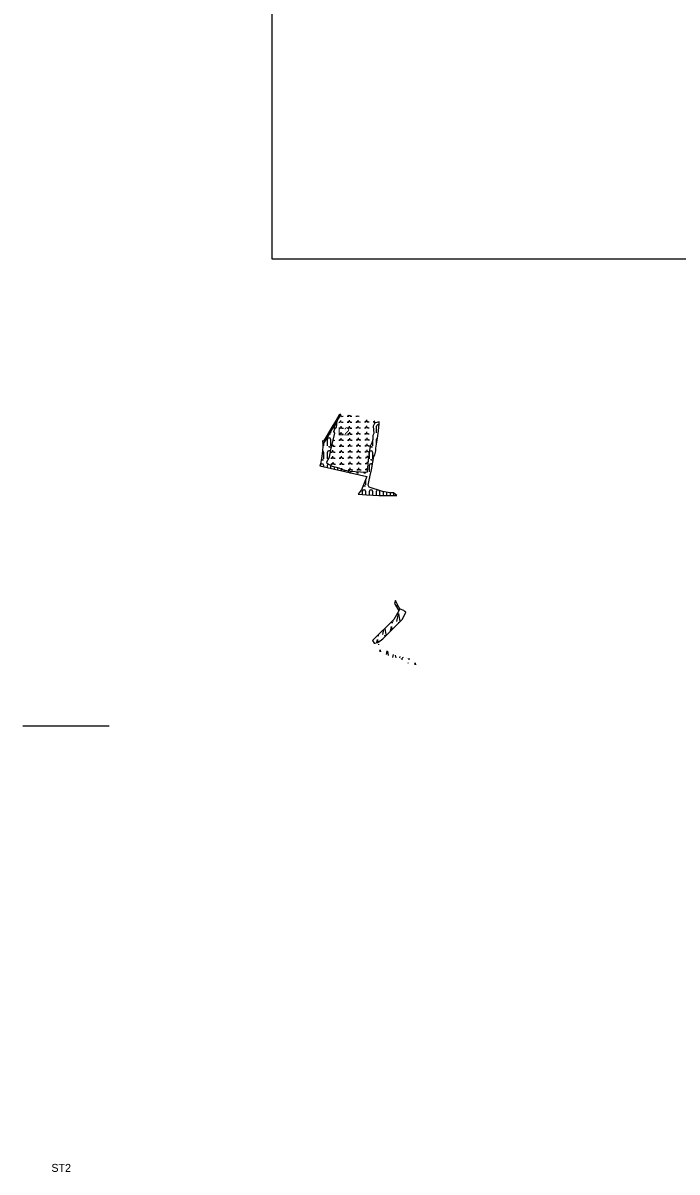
# Model space of a CAD drawing. Extents: x -557103 to -548162, y -1041918 to -1033974.
# Drawn here: x -556985 to -555351, y -1041918 to -1039045 of the extents above; entities that cross this region are included whole.
import ezdxf

# ---------------------------------------------------------------- set-up
doc = ezdxf.new("R2010")
doc.units = 0
for name, color, linetype in [('Vrstva 12', 7, 'Continuous'), ('Vrstva 13', 7, 'Continuous'), ('Vrstva 16', 7, 'Continuous'), ('Vrstva 63', 7, 'Continuous'), ('Vrstva 9', 7, 'Continuous')]:
    doc.layers.add(name, color=color, linetype=linetype)

msp = doc.modelspace()

# ---------------------------------------------------------------- linework, layer by layer
at = {"layer": 'Vrstva 12'}
for p, q in [((-556192.9, -1040028.7), (-556192.2, -1040028.7)), ((-556192.2, -1040028.7), (-556192.7, -1040027.7)), ((-556190.7, -1040028.2), (-556190.8, -1040023.8)), ((-556189.4, -1040028.7), (-556188.3, -1040026.3)), ((-556189.4, -1040028.7), (-556184.9, -1040028.6)), ((-556174.9, -1040028.4), (-556170.8, -1040028.3)), ((-556170.8, -1040028.3), (-556171.8, -1040026)), ((-556169.2, -1040027.8), (-556169.3, -1040025.4)), ((-556167.9, -1040028.3), (-556166.8, -1040026)), ((-556167.9, -1040028.3), (-556163.4, -1040028.3)), ((-556153.4, -1040028), (-556149.3, -1040028)), ((-556149.3, -1040028), (-556149.7, -1040027)), ((-556147.8, -1040027.4), (-556147.8, -1040027.4)), ((-556146.4, -1040028), (-556146.3, -1040027.7)), ((-556146.4, -1040028), (-556144.9, -1040027.9)), ((-556126, -1040042), (-556126.1, -1040037.6)), ((-556208.2, -1040066.7), (-556204.8, -1040058.2)), ((-556206.6, -1040062.6), (-556206.6, -1040053)), ((-556204.8, -1040058.2), (-556201.5, -1040055.4)), ((-556201.5, -1040055.4), (-556199.6, -1040039.7)), ((-556196.1, -1040043.7), (-556192, -1040043.6)), ((-556195.9, -1040058.6), (-556191.7, -1040058.5)), ((-556192, -1040043.6), (-556193, -1040041.3)), ((-556191.7, -1040058.5), (-556192.8, -1040056.2)), ((-556190.5, -1040043.1), (-556190.5, -1040038.7)), ((-556190.2, -1040058), (-556190.3, -1040053.6)), ((-556189.1, -1040043.6), (-556188, -1040041.2)), ((-556189.1, -1040043.6), (-556184.7, -1040043.6)), ((-556188.9, -1040058.5), (-556187.8, -1040056.2)), ((-556188.9, -1040058.5), (-556184.4, -1040058.5)), ((-556174.7, -1040043.3), (-556170.5, -1040043.2)), ((-556174.4, -1040058.2), (-556170.2, -1040058.1)), ((-556170.5, -1040043.2), (-556171.5, -1040040.9)), ((-556170.2, -1040058.1), (-556171.3, -1040055.8)), ((-556169, -1040042.7), (-556169.1, -1040038.4)), ((-556168.7, -1040057.6), (-556168.8, -1040053.3)), ((-556167.6, -1040043.3), (-556166.6, -1040040.9)), ((-556167.6, -1040043.3), (-556163.2, -1040043.2)), ((-556167.4, -1040058.2), (-556166.3, -1040055.8)), ((-556167.4, -1040058.2), (-556162.9, -1040058.1)), ((-556153.2, -1040042.9), (-556149, -1040042.9)), ((-556152.9, -1040057.8), (-556148.8, -1040057.8)), ((-556149, -1040042.9), (-556150.1, -1040040.5)), ((-556148.8, -1040057.8), (-556149.8, -1040055.4)), ((-556147.5, -1040042.3), (-556147.6, -1040038)), ((-556147.2, -1040057.2), (-556147.3, -1040052.9)), ((-556146.2, -1040042.9), (-556145.1, -1040040.5)), ((-556146.2, -1040042.9), (-556141.7, -1040042.8)), ((-556145.9, -1040057.8), (-556144.8, -1040055.4)), ((-556145.9, -1040057.8), (-556141.4, -1040057.7)), ((-556131.7, -1040042.6), (-556127.5, -1040042.5)), ((-556131.4, -1040057.5), (-556127.3, -1040057.4)), ((-556127.5, -1040042.5), (-556128.6, -1040040.1)), ((-556127.3, -1040057.4), (-556128.3, -1040055.1)), ((-556125.8, -1040056.9), (-556125.8, -1040052.5)), ((-556124.7, -1040042.5), (-556123.6, -1040040.1)), ((-556124.7, -1040042.5), (-556120.2, -1040042.4)), ((-556124.4, -1040057.4), (-556123.3, -1040055)), ((-556124.4, -1040057.4), (-556120, -1040057.3)), ((-556110.2, -1040042.2), (-556106.1, -1040042.1)), ((-556106.2, -1040046.2), (-556110.1, -1040053.6)), ((-556110.1, -1040053.6), (-556108.5, -1040071.6)), ((-556110, -1040057.1), (-556109.8, -1040057.1)), ((-556106.1, -1040042.1), (-556107.1, -1040039.8)), ((-556104.3, -1040044.9), (-556106.2, -1040046.2)), ((-556095.2, -1040042.7), (-556104.3, -1040044.9)), ((-556101.6, -1040069.5), (-556101.6, -1040053)), ((-556099.4, -1040083), (-556097, -1040065.3)), ((-556097, -1040065.3), (-556095.3, -1040047.6)), ((-556095.3, -1040047.6), (-556095.2, -1040042.7)), ((-556224.1, -1040102.1), (-556224.1, -1040085.6)), ((-556216.6, -1040067.1), (-556216.6, -1040069.5)), ((-556216.6, -1040085.6), (-556216.6, -1040102.1)), ((-556216.1, -1040112.6), (-556205.6, -1040070.7)), ((-556209.8, -1040088.7), (-556208.7, -1040086.3)), ((-556209.8, -1040088.7), (-556205.4, -1040088.6)), ((-556205.6, -1040070.7), (-556208.2, -1040066.7)), ((-556206.6, -1040069.5), (-556206.6, -1040069.2)), ((-556206.4, -1040073.7), (-556205.6, -1040073.7)), ((-556195.6, -1040073.5), (-556191.5, -1040073.4)), ((-556195.4, -1040088.4), (-556191.2, -1040088.3)), ((-556191.5, -1040073.4), (-556192.5, -1040071.1)), ((-556191.2, -1040088.3), (-556192.2, -1040086)), ((-556189.9, -1040072.9), (-556190, -1040068.6)), ((-556189.7, -1040087.8), (-556189.8, -1040083.5)), ((-556188.6, -1040073.4), (-556187.5, -1040071.1)), ((-556188.6, -1040073.4), (-556184.1, -1040073.4)), ((-556188.3, -1040088.3), (-556187.3, -1040086)), ((-556188.3, -1040088.3), (-556183.9, -1040088.3)), ((-556174.1, -1040073.1), (-556170, -1040073.1)), ((-556173.9, -1040088), (-556169.7, -1040088)), ((-556170, -1040073.1), (-556171, -1040070.7)), ((-556169.7, -1040088), (-556170.8, -1040085.6)), ((-556168.5, -1040072.5), (-556168.5, -1040068.2)), ((-556168.2, -1040087.4), (-556168.3, -1040083.1)), ((-556167.1, -1040073.1), (-556166, -1040070.7)), ((-556167.1, -1040073.1), (-556162.7, -1040073)), ((-556166.9, -1040088), (-556165.8, -1040085.6)), ((-556166.9, -1040088), (-556162.4, -1040087.9)), ((-556152.7, -1040072.7), (-556148.5, -1040072.7)), ((-556152.4, -1040087.7), (-556148.2, -1040087.6)), ((-556148.5, -1040072.7), (-556149.5, -1040070.3)), ((-556148.2, -1040087.6), (-556149.3, -1040085.2)), ((-556147, -1040072.2), (-556147.1, -1040067.8)), ((-556146.7, -1040087.1), (-556146.8, -1040082.7)), ((-556145.6, -1040072.7), (-556144.6, -1040070.3)), ((-556145.6, -1040072.7), (-556141.2, -1040072.6)), ((-556145.4, -1040087.6), (-556144.3, -1040085.2)), ((-556145.4, -1040087.6), (-556140.9, -1040087.5)), ((-556131.2, -1040072.4), (-556127, -1040072.3)), ((-556130.9, -1040087.3), (-556126.8, -1040087.2)), ((-556127, -1040072.3), (-556128.1, -1040070)), ((-556126.8, -1040087.2), (-556127.8, -1040084.9)), ((-556125.5, -1040071.8), (-556125.6, -1040067.4)), ((-556125.2, -1040086.7), (-556125.3, -1040082.3)), ((-556124.2, -1040072.3), (-556123.1, -1040069.9)), ((-556124.2, -1040072.3), (-556119.7, -1040072.2)), ((-556123.9, -1040087.2), (-556122.8, -1040084.8)), ((-556123.9, -1040087.2), (-556119.4, -1040087.1)), ((-556112.9, -1040095.2), (-556117.3, -1040102.9)), ((-556110.6, -1040086.2), (-556112.9, -1040095.2)), ((-556111.6, -1040090), (-556111.6, -1040102.1)), ((-556110.4, -1040076.8), (-556110.6, -1040086.2)), ((-556108.5, -1040071.6), (-556110.4, -1040076.8)), ((-556103.5, -1040108.5), (-556099.4, -1040083)), ((-556101.6, -1040096.7), (-556101.6, -1040085.6)), ((-556236.5, -1040115.5), (-556239.3, -1040133.8)), ((-556235.5, -1040102.4), (-556236.5, -1040115.5)), ((-556235.4, -1040097.9), (-556235.5, -1040102.4)), ((-556234.1, -1040095.8), (-556234.1, -1040102.1)), ((-556234.1, -1040118.1), (-556234.1, -1040134.6)), ((-556224.1, -1040134.6), (-556224.1, -1040118.1)), ((-556219, -1040130.7), (-556216.1, -1040112.6)), ((-556216.3, -1040118.6), (-556212.2, -1040118.5)), ((-556213.9, -1040103.6), (-556212.4, -1040103.6)), ((-556212.4, -1040103.6), (-556213.3, -1040101.5)), ((-556212.2, -1040118.5), (-556213.2, -1040116.2)), ((-556210.9, -1040103.1), (-556211, -1040098.7)), ((-556210.6, -1040118), (-556210.7, -1040113.6)), ((-556209.6, -1040103.6), (-556208.5, -1040101.2)), ((-556209.6, -1040103.6), (-556205.1, -1040103.5)), ((-556209.3, -1040118.5), (-556208.2, -1040116.1)), ((-556209.3, -1040118.5), (-556204.8, -1040118.5)), ((-556195.1, -1040103.3), (-556190.9, -1040103.2)), ((-556194.8, -1040118.2), (-556190.7, -1040118.1)), ((-556190.9, -1040103.2), (-556192, -1040100.9)), ((-556190.7, -1040118.1), (-556191.7, -1040115.8)), ((-556189.4, -1040102.7), (-556189.5, -1040098.4)), ((-556189.2, -1040117.6), (-556189.2, -1040113.3)), ((-556188.1, -1040103.2), (-556187, -1040100.9)), ((-556188.1, -1040103.2), (-556183.6, -1040103.2)), ((-556187.8, -1040118.2), (-556186.7, -1040115.8)), ((-556187.8, -1040118.2), (-556183.4, -1040118.1)), ((-556173.6, -1040102.9), (-556169.5, -1040102.9)), ((-556173.4, -1040117.8), (-556169.2, -1040117.8)), ((-556169.5, -1040102.9), (-556170.5, -1040100.5)), ((-556169.2, -1040117.8), (-556170.2, -1040115.4)), ((-556167.9, -1040102.3), (-556168, -1040098)), ((-556167.7, -1040117.2), (-556167.8, -1040112.9)), ((-556166.6, -1040102.9), (-556165.5, -1040100.5)), ((-556166.6, -1040102.9), (-556162.1, -1040102.8)), ((-556166.3, -1040117.8), (-556165.3, -1040115.4)), ((-556166.3, -1040117.8), (-556161.9, -1040117.7)), ((-556152.1, -1040102.6), (-556148, -1040102.5)), ((-556151.9, -1040117.5), (-556147.7, -1040117.4)), ((-556148, -1040102.5), (-556149, -1040100.1)), ((-556147.7, -1040117.4), (-556148.8, -1040115)), ((-556146.5, -1040102), (-556146.5, -1040097.6)), ((-556146.2, -1040116.9), (-556146.3, -1040112.5)), ((-556145.1, -1040102.5), (-556144, -1040100.1)), ((-556145.1, -1040102.5), (-556140.7, -1040102.4)), ((-556144.9, -1040117.4), (-556143.8, -1040115)), ((-556144.9, -1040117.4), (-556140.4, -1040117.3)), ((-556130.7, -1040102.2), (-556126.5, -1040102.1)), ((-556130.4, -1040117.1), (-556126.2, -1040117)), ((-556126.5, -1040102.1), (-556127.5, -1040099.8)), ((-556126.2, -1040117), (-556127.3, -1040114.7)), ((-556125, -1040101.6), (-556125.1, -1040097.2)), ((-556124.7, -1040116.5), (-556124.8, -1040112.1)), ((-556123.6, -1040102.1), (-556122.6, -1040099.7)), ((-556123.6, -1040102.1), (-556119.2, -1040102)), ((-556123.4, -1040117), (-556122.3, -1040114.6)), ((-556123.4, -1040117), (-556119.6, -1040117)), ((-556117.3, -1040102.9), (-556120.8, -1040124.4)), ((-556119.1, -1040134.6), (-556119.1, -1040118.1)), ((-556111.6, -1040118.1), (-556111.6, -1040134.6)), ((-556105.6, -1040124.8), (-556103.3, -1040114.8)), ((-556103.3, -1040114.8), (-556103.5, -1040108.5)), ((-556241.8, -1040147.6), (-556242.9, -1040152.6)), ((-556242.9, -1040152.6), (-556125.7, -1040179.3)), ((-556239.3, -1040133.8), (-556241.8, -1040147.6)), ((-556241.6, -1040152.9), (-556241.6, -1040150.6)), ((-556234.1, -1040150.6), (-556234.1, -1040154.6)), ((-556225.7, -1040142.2), (-556219, -1040130.7)), ((-556225.1, -1040146.5), (-556225.7, -1040142.2)), ((-556211.4, -1040154), (-556225.1, -1040146.5)), ((-556224.1, -1040156.9), (-556224.1, -1040150.6)), ((-556216.6, -1040151.2), (-556216.6, -1040158.6)), ((-556216.1, -1040133.5), (-556211.9, -1040133.4)), ((-556215.8, -1040148.4), (-556211.6, -1040148.3)), ((-556211.9, -1040133.4), (-556212.9, -1040131.1)), ((-556211.6, -1040148.3), (-556212.7, -1040146)), ((-556210.4, -1040132.9), (-556210.5, -1040128.6)), ((-556210.1, -1040147.8), (-556210.2, -1040143.5)), ((-556209, -1040133.4), (-556208, -1040131.1)), ((-556209, -1040133.4), (-556204.6, -1040133.4)), ((-556208.8, -1040148.3), (-556207.7, -1040146)), ((-556208.8, -1040148.3), (-556204.3, -1040148.3)), ((-556194.6, -1040133.1), (-556190.4, -1040133)), ((-556194.3, -1040148), (-556190.2, -1040148)), ((-556190.4, -1040133), (-556191.5, -1040130.7)), ((-556190.2, -1040148), (-556191.2, -1040145.6)), ((-556188.9, -1040132.5), (-556189, -1040128.2)), ((-556188.6, -1040147.4), (-556188.7, -1040143.1)), ((-556187.6, -1040133.1), (-556186.5, -1040130.7)), ((-556187.6, -1040133.1), (-556183.1, -1040133)), ((-556187.3, -1040148), (-556186.2, -1040145.6)), ((-556187.3, -1040148), (-556182.8, -1040147.9)), ((-556173.1, -1040132.7), (-556168.9, -1040132.7)), ((-556172.8, -1040147.7), (-556168.7, -1040147.6)), ((-556168.9, -1040132.7), (-556170, -1040130.3)), ((-556168.7, -1040147.6), (-556169.7, -1040145.2)), ((-556167.4, -1040132.1), (-556167.5, -1040127.8)), ((-556167.2, -1040147.1), (-556167.2, -1040142.7)), ((-556166.1, -1040132.7), (-556165, -1040130.3)), ((-556166.1, -1040132.7), (-556161.6, -1040132.6)), ((-556165.8, -1040147.6), (-556164.7, -1040145.2)), ((-556165.8, -1040147.6), (-556161.4, -1040147.5)), ((-556151.6, -1040132.4), (-556147.5, -1040132.3)), ((-556151.4, -1040147.3), (-556147.2, -1040147.2)), ((-556147.5, -1040132.3), (-556148.5, -1040130)), ((-556147.2, -1040147.2), (-556148.2, -1040144.9)), ((-556145.9, -1040131.8), (-556146, -1040127.4)), ((-556145.7, -1040146.7), (-556145.8, -1040142.3)), ((-556144.6, -1040132.3), (-556143.5, -1040129.9)), ((-556144.6, -1040132.3), (-556140.1, -1040132.2)), ((-556144.3, -1040147.2), (-556143.3, -1040144.8)), ((-556144.3, -1040147.2), (-556139.9, -1040147.1)), ((-556130.1, -1040132), (-556126, -1040131.9)), ((-556129.9, -1040146.9), (-556125.7, -1040146.8)), ((-556126, -1040131.9), (-556127, -1040129.6)), ((-556125.7, -1040146.8), (-556126.7, -1040144.5)), ((-556124.5, -1040131.4), (-556124.5, -1040127.1)), ((-556123.2, -1040146.8), (-556124.5, -1040158.1)), ((-556124.2, -1040146.3), (-556124.3, -1040142)), ((-556120.8, -1040124.4), (-556123.2, -1040146.8)), ((-556123.1, -1040131.9), (-556122, -1040129.6)), ((-556123.1, -1040131.9), (-556121.6, -1040131.9)), ((-556120.8, -1040124.4), (-556120.8, -1040124.4)), ((-556119.1, -1040167.1), (-556119.1, -1040150.6)), ((-556114.2, -1040162.7), (-556107.9, -1040129.2)), ((-556107.9, -1040129.2), (-556105.6, -1040124.8)), ((-556194.9, -1040158.3), (-556211.4, -1040154)), ((-556206.6, -1040160.9), (-556206.6, -1040155.3)), ((-556199.1, -1040157.2), (-556199.1, -1040162.6)), ((-556183.9, -1040163.1), (-556194.9, -1040158.3)), ((-556189.1, -1040164.9), (-556189.1, -1040160.8)), ((-556188.4, -1040161.1), (-556188.5, -1040158)), ((-556186.6, -1040161.9), (-556186, -1040160.5)), ((-556184.6, -1040162.8), (-556182.6, -1040162.8)), ((-556167.1, -1040166.2), (-556183.9, -1040163.1)), ((-556181.6, -1040163.5), (-556181.6, -1040166.6)), ((-556172.6, -1040162.6), (-556168.4, -1040162.5)), ((-556171.6, -1040167.1), (-556171.6, -1040165.4)), ((-556168.4, -1040162.5), (-556169.5, -1040160.1)), ((-556141.4, -1040168.6), (-556167.1, -1040166.2)), ((-556166.9, -1040162), (-556167, -1040157.6)), ((-556165.6, -1040162.5), (-556164.5, -1040160.1)), ((-556165.6, -1040162.5), (-556161.1, -1040162.4)), ((-556164.1, -1040166.5), (-556164.1, -1040167.1)), ((-556151.1, -1040162.2), (-556146.9, -1040162.1)), ((-556146.9, -1040162.1), (-556148, -1040159.8)), ((-556145.4, -1040161.6), (-556145.5, -1040157.2)), ((-556144.1, -1040162.1), (-556143, -1040159.7)), ((-556144.1, -1040162.1), (-556139.6, -1040162)), ((-556128.1, -1040168.9), (-556141.4, -1040168.6)), ((-556125.7, -1040179.3), (-556139.2, -1040212)), ((-556129.6, -1040161.8), (-556125.5, -1040161.7)), ((-556124.7, -1040168.3), (-556128.1, -1040168.9)), ((-556125.5, -1040161.7), (-556126.5, -1040159.4)), ((-556124.5, -1040158.1), (-556124.7, -1040168.3)), ((-556122.5, -1040200.7), (-556118.3, -1040179.7)), ((-556118.3, -1040179.7), (-556114.2, -1040162.7)), ((-556129.1, -1040187.4), (-556129.1, -1040199.6)), ((-556119.9, -1040205.9), (-556122.5, -1040200.7)), ((-556086.5, -1040216.9), (-556119.9, -1040205.9)), ((-556119.1, -1040183.7), (-556119.1, -1040183.1)), ((-556142.1, -1040216.3), (-556147.4, -1040223.6)), ((-556147.4, -1040223.6), (-556126.8, -1040224.7)), ((-556146.6, -1040222.4), (-556146.6, -1040223.6)), ((-556139.2, -1040212), (-556142.1, -1040216.3)), ((-556136.6, -1040224.2), (-556136.6, -1040215.6)), ((-556129.1, -1040215.6), (-556129.1, -1040224.6)), ((-556126.8, -1040224.7), (-556095.8, -1040226.3)), ((-556119.1, -1040225.1), (-556119.1, -1040215.6)), ((-556111.6, -1040215.6), (-556111.6, -1040225.5)), ((-556101.6, -1040226), (-556101.6, -1040215.6)), ((-556095.8, -1040226.3), (-556051.1, -1040226.3)), ((-556094.1, -1040215.6), (-556094.1, -1040226.3)), ((-556067.7, -1040219.5), (-556086.5, -1040216.9)), ((-556084.1, -1040226.3), (-556084.1, -1040217.3)), ((-556076.6, -1040218.3), (-556076.6, -1040226.3)), ((-556059.5, -1040219.7), (-556067.7, -1040219.5)), ((-556066.6, -1040226.3), (-556066.6, -1040219.6)), ((-556051.1, -1040226.3), (-556059.5, -1040219.7)), ((-556059.1, -1040220), (-556059.1, -1040226.3))]:
    msp.add_line(p, q, dxfattribs=at)
for points in [[(-556199.6, -1040039.7), (-556210.7, -1040057.1), (-556224.4, -1040080.7), (-556230.7, -1040090.5), (-556235.4, -1040097.9)], [(-556219.4, -1040072), (-556216.6, -1040072)], [(-556098.1, -1040071), (-556098.1, -1040072), (-556097.9, -1040072)], [(-556235.7, -1040104.6), (-556234.1, -1040104.6)], [(-556220.6, -1040103.6), (-556220.6, -1040104.6), (-556216.6, -1040104.6)], [(-556115.6, -1040103.6), (-556115.6, -1040104.6), (-556111.6, -1040104.6)], [(-556238.1, -1040136.1), (-556238.1, -1040137.1), (-556234.1, -1040137.1)], [(-556115.6, -1040136.1), (-556115.6, -1040137.1), (-556111.6, -1040137.1)], [(-556168.1, -1040168.6), (-556168.1, -1040169.6), (-556164.1, -1040169.6)], [(-556150.6, -1040168.6), (-556150.6, -1040169.6), (-556146.6, -1040169.6)], [(-556133.1, -1040168.8), (-556133.1, -1040169.6), (-556129.1, -1040169.6)], [(-556133.1, -1040201.1), (-556133.1, -1040202.1), (-556129.1, -1040202.1)]]:
    msp.add_lwpolyline(points, dxfattribs=at)
for centre, start_param, end_param in [((-556202.8, -1040053), 4.164436, 6.283185), ((-556097.8, -1040053), 4.062123, 6.283185), ((-556220.3, -1040085.6), 3.141593, 6.283185), ((-556097.8, -1040085.6), 5.117932, 6.283185), ((-556237.8, -1040118.1), 3.141593, 4.343916), ((-556220.3, -1040118.1), 3.502099, 6.283185), ((-556115.3, -1040118.1), 3.141593, 6.283185), ((-556237.8, -1040150.6), 3.141593, 6.283185), ((-556220.3, -1040150.6), 5.380933, 6.283185), ((-556115.3, -1040150.6), 3.462815, 6.283185), ((-556115.3, -1040183.1), 5.779687, 6.283185), ((-556132.8, -1040215.6), 3.141593, 6.283185), ((-556115.3, -1040215.6), 3.141593, 6.283185), ((-556097.8, -1040215.6), 5.245901, 6.283185), ((-556097.8, -1040215.6), 3.141593, 3.498411)]:
    msp.add_ellipse(centre, major_axis=(-3.75, 0), ratio=0.935414, start_param=start_param, end_param=end_param, dxfattribs=at)
at = {"layer": 'Vrstva 13'}
msp.add_line((-556985, -1040802.6), (-556769.8, -1040802.6), dxfattribs=at)
msp.add_lwpolyline([(-556098.5, -1040593.6), (-556085.5, -1040584.8), (-556036.8, -1040535.4), (-556028.4, -1040518.5), (-556030.6, -1040516.7), (-556033.4, -1040513.9), (-556042.1, -1040510.5), (-556046, -1040505.4), (-556053.7, -1040491.1), (-556054.4, -1040489.4), (-556056.7, -1040496.4), (-556045.6, -1040514.9), (-556058, -1040536.5), (-556111.2, -1040589.4), (-556107.3, -1040595.9)], close=True, dxfattribs=at)
for points in [[(-556050.5, -1040541.7), (-556047, -1040521.7), (-556043, -1040541.6)], [(-556050.1, -1040507.4), (-556048.9, -1040500.1)], [(-556047, -1040510.7), (-556047, -1040511.7), (-556043, -1040511.7)], [(-556066.4, -1040565.4), (-556064.5, -1040554.2), (-556062.9, -1040561.8)], [(-556064.5, -1040543.2), (-556064.5, -1040544.2), (-556060.5, -1040544.2)], [(-556060.9, -1040539.4), (-556060.5, -1040541.7)], [(-556047, -1040543.2), (-556047, -1040544.2), (-556045.5, -1040544.2)], [(-556098.5, -1040576.7), (-556095.5, -1040576.7)], [(-556095.5, -1040573.8), (-556095.5, -1040574.2)], [(-556085.5, -1040574.2), (-556083.2, -1040561.6)], [(-556082, -1040575.7), (-556082, -1040576.7), (-556078, -1040576.7)], [(-556080.9, -1040559.3), (-556078, -1040574.2)], [(-556106.8, -1040595.8), (-556106.4, -1040597.4)], [(-556100.8, -1040594.2), (-556099.5, -1040586.7), (-556098.1, -1040593.3)], [(-556095.9, -1040600.2), (-556095.6, -1040598.5)], [(-556093.1, -1040616.9), (-556092.4, -1040612.7), (-556091.4, -1040617.7)], [(-556076.9, -1040624.3), (-556075.3, -1040615.2)], [(-556074.3, -1040615.8), (-556072.1, -1040626.5)], [(-556060.7, -1040631.7), (-556059.3, -1040623.6)], [(-556054.9, -1040625.3), (-556053.4, -1040632.7)], [(-556043.4, -1040632.7), (-556042.7, -1040628.6)], [(-556039.9, -1040634.2), (-556039.9, -1040635.2), (-556035.9, -1040635.2)], [(-556036.4, -1040630), (-556035.9, -1040632.7)], [(-556025.9, -1040632.7), (-556025.8, -1040632.4)], [(-556022.4, -1040634.2), (-556022.4, -1040635.2), (-556018.4, -1040635.2)], [(-556022.5, -1040645.8), (-556022.4, -1040645.2), (-556022.3, -1040645.9)], [(-556005.6, -1040649.4), (-556004.9, -1040645.2), (-556004, -1040649.8)]]:
    msp.add_lwpolyline(points, dxfattribs=at)
at = {"layer": 'Vrstva 63'}
msp.add_lwpolyline([(-550519.3, -1039635.9), (-556362.3, -1039635.9), (-556362.3, -1034682.3), (-550519.3, -1034682.3)], close=True, dxfattribs=at)
at = {"layer": 'Vrstva 9'}
msp.add_lwpolyline([(-556236.2, -1040090.2), (-556235.4, -1040097.9), (-556230.7, -1040090.5), (-556224.4, -1040080.7), (-556210.7, -1040057.1), (-556199.6, -1040039.7), (-556192.9, -1040028.8), (-556191.7, -1040023.1), (-556195.2, -1040024.7), (-556202.7, -1040038.3), (-556213.4, -1040055.7), (-556227.4, -1040080), (-556234.4, -1040090.9)], close=True, dxfattribs=at)

# ---------------------------------------------------------------- texts
at = {"layer": 'Vrstva 16'}
for s, p in [('L2', (-556198, -1040076.4)), ('ST2', (-556914.1, -1041917.4))]:
    msp.add_text(s, height=20, dxfattribs=at).set_placement(p)

doc.saveas('drawing.dxf')
